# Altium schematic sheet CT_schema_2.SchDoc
size 294 x 169 mm
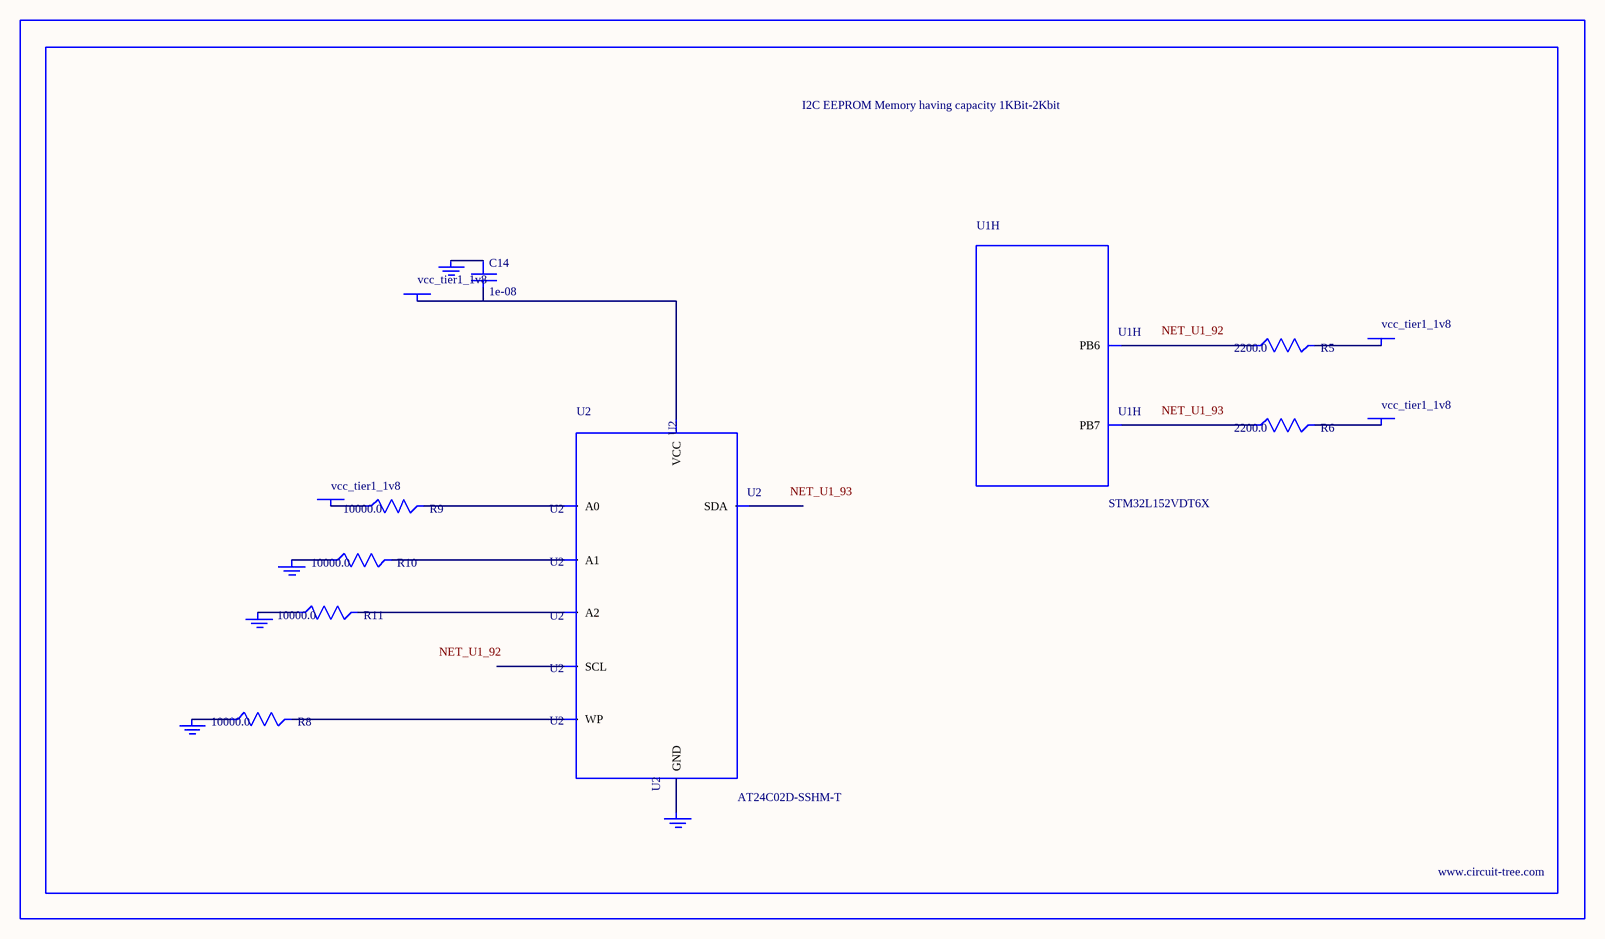
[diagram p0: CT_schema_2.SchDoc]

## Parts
BORDER1  (no value)
C14  1e-08  [C0402]
GND_INSTANCE_1_0  (no value)
GND_INSTANCE_1_1  (no value)
GND_INSTANCE_1_2  (no value)
GND_INSTANCE_1_3  (no value)
GND_INSTANCE_1_4  (no value)
POWER_INSTANCE_1_0  vcc_tier1_1v8
POWER_INSTANCE_1_1  vcc_tier1_1v8
POWER_INSTANCE_1_2  vcc_tier1_1v8
POWER_INSTANCE_1_3  vcc_tier1_1v8
R5  2200.0  [R0603]
R6  2200.0  [R0603]
R8  10000.0  [R0603]
R9  10000.0  [R0603]
R10  10000.0  [R0603]
R11  10000.0  [R0603]
U1  STM32L152VDT6X  [LQFP100]  (part H of 8)
U2  AT24C02D-SSHM-T  [AT24C02D]

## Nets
NetC14_1: C14.1 GND_INSTANCE_1_3.0(GND)
NetC14_2: C14.2 POWER_INSTANCE_1_1.0(PWR) U2.8(VCC)
NetGND_INSTANCE_1_0_0: GND_INSTANCE_1_0.0(GND) R10.1
NetGND_INSTANCE_1_1_0: GND_INSTANCE_1_1.0(GND) R11.1
NetGND_INSTANCE_1_2_0: GND_INSTANCE_1_2.0(GND) R8.1
NetGND_INSTANCE_1_4_0: GND_INSTANCE_1_4.0(GND) U2.4(GND)
NetPOWER_INSTANCE_1_0_0: POWER_INSTANCE_1_0.0(PWR) R9.1
NetPOWER_INSTANCE_1_2_0: POWER_INSTANCE_1_2.0(PWR) R5.2
NetPOWER_INSTANCE_1_3_0: POWER_INSTANCE_1_3.0(PWR) R6.2
NetR5_1: R5.1 U1.92(PB6)
NetR6_1: R6.1 U1.93(PB7)
NetR8_2: R8.2 U2.7(WP)
NetR9_2: R9.2 U2.1(A0)
NetR10_2: R10.2 U2.2(A1)
NetR11_2: R11.2 U2.3(A2)

Not connected (* = marked no-connect by the designer): U2 5(SDA) 6(SCL)

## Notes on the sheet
- Labels drawn without touching a wire or pin: NET_U1_92, NET_U1_93

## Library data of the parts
BORDER1 = BORDER_PAGE1
C14 = C0402C103K3RAC
GND_INSTANCE_1_0-GND_INSTANCE_1_4 = GND
POWER_INSTANCE_1_0-POWER_INSTANCE_1_3 = PWR
R5 R6 = RC0603JR-072K2L
R8-R11 = RC0603JR-0710KL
